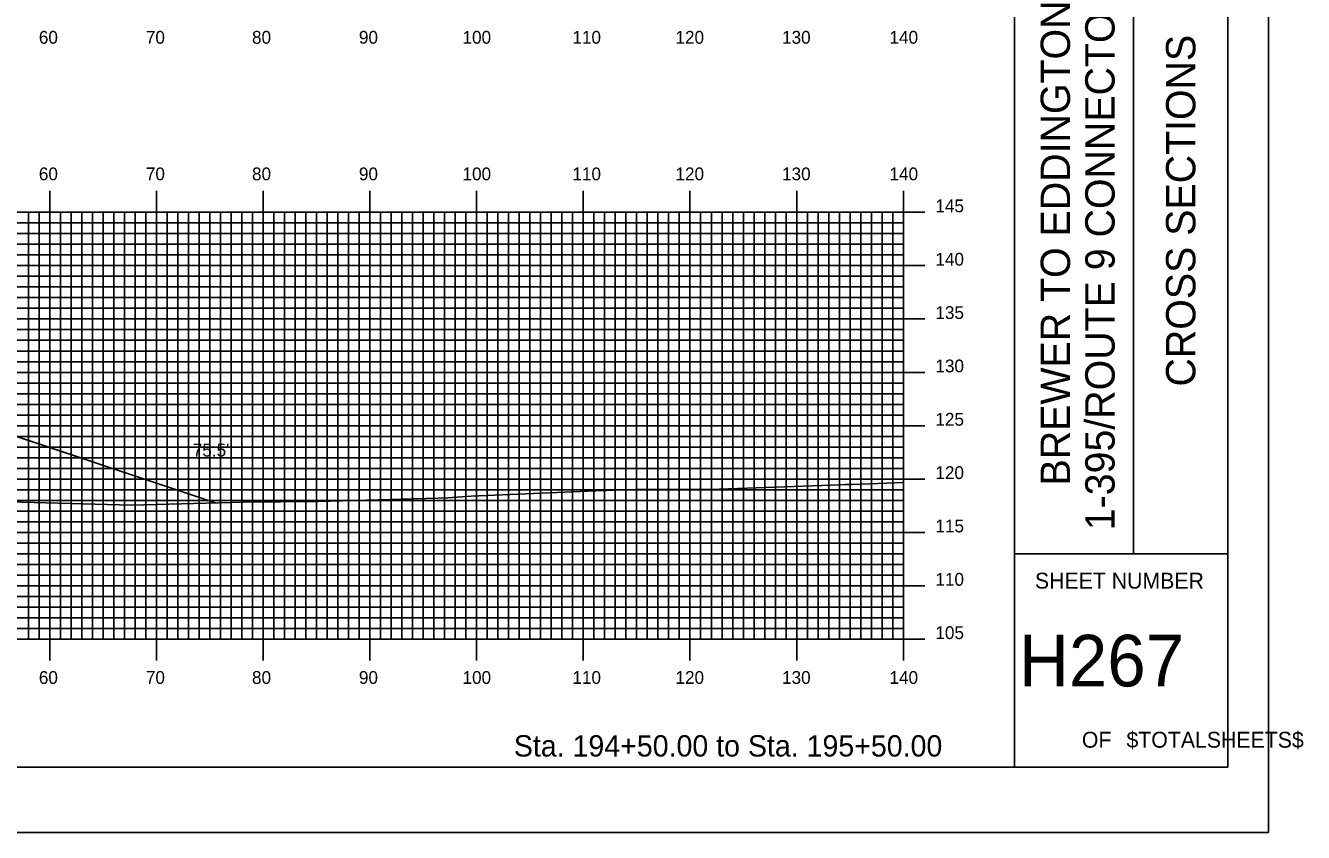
# Model space of a CAD drawing. Extents: x 1789337 to 1789680, y 442591 to 442811.
# Drawn here: x 1789560.4 to 1789680.2, y 442590.5 to 442666.2 of the extents above; entities that cross this region are included whole.
import ezdxf

# ---------------------------------------------------------------- set-up
doc = ezdxf.new("R2010")
doc.units = 0
for name, color, linetype in [('BORDER', 7, 'Continuous'), ('D_Roadway_Centerline', 7, 'Continuous'), ('D_Roadway_SlopeLines', 7, 'Continuous'), ('D_Text_Standard', 7, 'Continuous'), ('H_V ANNOTATION', 7, 'Continuous'), ('MAJOR', 7, 'Continuous'), ('MINOR', 7, 'Continuous'), ('PLOT BOUNDARY', 7, 'Continuous'), ('S_Roadway_Centerline', 7, 'Continuous')]:
    doc.layers.add(name, color=color, linetype=linetype)

msp = doc.modelspace()

# ---------------------------------------------------------------- linework, layer by layer
at = {"layer": 'BORDER'}
for p, q in [((1789653.07, 442596.67), (1789653.07, 442806.67)), ((1789664.25, 442616.67), (1789664.25, 442686.67)), ((1789653.07, 442616.67), (1789673.07, 442616.67))]:
    msp.add_line(p, q, dxfattribs=at)
msp.add_lwpolyline([(1789353.07, 442596.67), (1789673.07, 442596.67), (1789673.07, 442806.67), (1789353.07, 442806.67)], close=True, dxfattribs=at)
at = {"layer": 'D_Roadway_Centerline'}
msp.add_lwpolyline([(1789424.26, 442619.51), (1789472.46, 442635.96), (1789479.67, 442638.42), (1789482.67, 442638.54), (1789490.67, 442638.86), (1789502.67, 442639.12), (1789514.67, 442639.39), (1789522.67, 442639.07), (1789525.67, 442638.95), (1789532.95, 442636.52), (1789578.2, 442621.44)], dxfattribs=at)
at = {"layer": 'D_Roadway_SlopeLines'}
msp.add_lwpolyline([(1789525.67, 442638.95), (1789578.2, 442621.44)], dxfattribs=at)
at = {"layer": 'MAJOR'}
for p, q in [((1789562.67, 442650.67), (1789562.67, 442648.67)), ((1789572.67, 442650.67), (1789572.67, 442648.67)), ((1789582.67, 442650.67), (1789582.67, 442648.67)), ((1789592.67, 442650.67), (1789592.67, 442648.67)), ((1789602.67, 442650.67), (1789602.67, 442648.67)), ((1789612.67, 442650.67), (1789612.67, 442648.67)), ((1789622.67, 442650.67), (1789622.67, 442648.67)), ((1789632.67, 442650.67), (1789632.67, 442648.67)), ((1789642.67, 442650.67), (1789642.67, 442648.67)), ((1789362.67, 442648.67), (1789642.67, 442648.67)), ((1789362.67, 442648.67), (1789642.67, 442648.67)), ((1789562.67, 442608.67), (1789562.67, 442648.67)), ((1789572.67, 442608.67), (1789572.67, 442648.67)), ((1789582.67, 442608.67), (1789582.67, 442648.67)), ((1789592.67, 442608.67), (1789592.67, 442648.67)), ((1789602.67, 442608.67), (1789602.67, 442648.67)), ((1789612.67, 442608.67), (1789612.67, 442648.67)), ((1789622.67, 442608.67), (1789622.67, 442648.67)), ((1789632.67, 442608.67), (1789632.67, 442648.67)), ((1789644.67, 442648.67), (1789640.67, 442648.67)), ((1789642.67, 442608.67), (1789642.67, 442648.67)), ((1789642.67, 442608.67), (1789642.67, 442648.67)), ((1789362.67, 442643.67), (1789642.67, 442643.67)), ((1789644.67, 442643.67), (1789640.67, 442643.67)), ((1789362.67, 442638.67), (1789642.67, 442638.67)), ((1789644.67, 442638.67), (1789640.67, 442638.67)), ((1789362.67, 442633.67), (1789642.67, 442633.67)), ((1789644.67, 442633.67), (1789640.67, 442633.67)), ((1789362.67, 442628.67), (1789642.67, 442628.67)), ((1789644.67, 442628.67), (1789640.67, 442628.67)), ((1789362.67, 442623.67), (1789642.67, 442623.67)), ((1789644.67, 442623.67), (1789640.67, 442623.67)), ((1789362.67, 442618.67), (1789642.67, 442618.67)), ((1789644.67, 442618.67), (1789640.67, 442618.67)), ((1789362.67, 442613.67), (1789642.67, 442613.67)), ((1789644.67, 442613.67), (1789640.67, 442613.67)), ((1789362.67, 442608.67), (1789642.67, 442608.67)), ((1789362.67, 442608.67), (1789642.67, 442608.67)), ((1789562.67, 442606.66), (1789562.67, 442608.67)), ((1789572.67, 442606.66), (1789572.67, 442608.67)), ((1789582.67, 442606.66), (1789582.67, 442608.67)), ((1789592.67, 442606.66), (1789592.67, 442608.67)), ((1789602.67, 442606.66), (1789602.67, 442608.67)), ((1789612.67, 442606.66), (1789612.67, 442608.67)), ((1789622.67, 442606.66), (1789622.67, 442608.67)), ((1789632.67, 442606.66), (1789632.67, 442608.67)), ((1789644.67, 442608.67), (1789640.67, 442608.67)), ((1789642.67, 442606.66), (1789642.67, 442608.67))]:
    msp.add_line(p, q, dxfattribs=at)
at = {"layer": 'MINOR'}
for p, q in [((1789362.67, 442647.67), (1789642.67, 442647.67)), ((1789560.67, 442608.67), (1789560.67, 442648.67)), ((1789561.67, 442608.67), (1789561.67, 442648.67)), ((1789563.67, 442608.67), (1789563.67, 442648.67)), ((1789564.67, 442608.67), (1789564.67, 442648.67)), ((1789565.67, 442608.67), (1789565.67, 442648.67)), ((1789566.67, 442608.67), (1789566.67, 442648.67)), ((1789567.67, 442608.67), (1789567.67, 442648.67)), ((1789568.67, 442608.67), (1789568.67, 442648.67)), ((1789569.67, 442608.67), (1789569.67, 442648.67)), ((1789570.67, 442608.67), (1789570.67, 442648.67)), ((1789571.67, 442608.67), (1789571.67, 442648.67)), ((1789573.67, 442608.67), (1789573.67, 442648.67)), ((1789574.67, 442608.67), (1789574.67, 442648.67)), ((1789575.67, 442608.67), (1789575.67, 442648.67)), ((1789576.67, 442608.67), (1789576.67, 442648.67)), ((1789577.67, 442608.67), (1789577.67, 442648.67)), ((1789578.67, 442608.67), (1789578.67, 442648.67)), ((1789579.67, 442608.67), (1789579.67, 442648.67)), ((1789580.67, 442608.67), (1789580.67, 442648.67)), ((1789581.67, 442608.67), (1789581.67, 442648.67)), ((1789583.67, 442608.67), (1789583.67, 442648.67)), ((1789584.67, 442608.67), (1789584.67, 442648.67)), ((1789585.67, 442608.67), (1789585.67, 442648.67)), ((1789586.67, 442608.67), (1789586.67, 442648.67)), ((1789587.67, 442608.67), (1789587.67, 442648.67)), ((1789588.67, 442608.67), (1789588.67, 442648.67)), ((1789589.67, 442608.67), (1789589.67, 442648.67)), ((1789590.67, 442608.67), (1789590.67, 442648.67)), ((1789591.67, 442608.67), (1789591.67, 442648.67)), ((1789593.67, 442608.67), (1789593.67, 442648.67)), ((1789594.67, 442608.67), (1789594.67, 442648.67)), ((1789595.67, 442608.67), (1789595.67, 442648.67)), ((1789596.67, 442608.67), (1789596.67, 442648.67)), ((1789597.67, 442608.67), (1789597.67, 442648.67)), ((1789598.67, 442608.67), (1789598.67, 442648.67)), ((1789599.67, 442608.67), (1789599.67, 442648.67)), ((1789600.67, 442608.67), (1789600.67, 442648.67)), ((1789601.67, 442608.67), (1789601.67, 442648.67)), ((1789603.67, 442608.67), (1789603.67, 442648.67)), ((1789604.67, 442608.67), (1789604.67, 442648.67)), ((1789605.67, 442608.67), (1789605.67, 442648.67)), ((1789606.67, 442608.67), (1789606.67, 442648.67)), ((1789607.67, 442608.67), (1789607.67, 442648.67)), ((1789608.67, 442608.67), (1789608.67, 442648.67)), ((1789609.67, 442608.67), (1789609.67, 442648.67)), ((1789610.67, 442608.67), (1789610.67, 442648.67)), ((1789611.67, 442608.67), (1789611.67, 442648.67)), ((1789613.67, 442608.67), (1789613.67, 442648.67)), ((1789614.67, 442608.67), (1789614.67, 442648.67)), ((1789615.67, 442608.67), (1789615.67, 442648.67)), ((1789616.67, 442608.67), (1789616.67, 442648.67)), ((1789617.67, 442608.67), (1789617.67, 442648.67)), ((1789618.67, 442608.67), (1789618.67, 442648.67)), ((1789619.67, 442608.67), (1789619.67, 442648.67)), ((1789620.67, 442608.67), (1789620.67, 442648.67)), ((1789621.67, 442608.67), (1789621.67, 442648.67)), ((1789623.67, 442608.67), (1789623.67, 442648.67)), ((1789624.67, 442608.67), (1789624.67, 442648.67)), ((1789625.67, 442608.67), (1789625.67, 442648.67)), ((1789626.67, 442608.67), (1789626.67, 442648.67)), ((1789627.67, 442608.67), (1789627.67, 442648.67)), ((1789628.67, 442608.67), (1789628.67, 442648.67)), ((1789629.67, 442608.67), (1789629.67, 442648.67)), ((1789630.67, 442608.67), (1789630.67, 442648.67)), ((1789631.67, 442608.67), (1789631.67, 442648.67)), ((1789633.67, 442608.67), (1789633.67, 442648.67)), ((1789634.67, 442608.67), (1789634.67, 442648.67)), ((1789635.67, 442608.67), (1789635.67, 442648.67)), ((1789636.67, 442608.67), (1789636.67, 442648.67)), ((1789637.67, 442608.67), (1789637.67, 442648.67)), ((1789638.67, 442608.67), (1789638.67, 442648.67)), ((1789639.67, 442608.67), (1789639.67, 442648.67)), ((1789640.67, 442608.67), (1789640.67, 442648.67)), ((1789642.67, 442647.67), (1789640.67, 442647.67)), ((1789641.67, 442608.67), (1789641.67, 442648.67)), ((1789362.67, 442646.67), (1789642.67, 442646.67)), ((1789642.67, 442646.67), (1789640.67, 442646.67)), ((1789362.67, 442645.67), (1789642.67, 442645.67)), ((1789642.67, 442645.67), (1789640.67, 442645.67)), ((1789362.67, 442644.67), (1789642.67, 442644.67)), ((1789642.67, 442644.67), (1789640.67, 442644.67)), ((1789362.67, 442642.67), (1789642.67, 442642.67)), ((1789362.67, 442641.67), (1789642.67, 442641.67)), ((1789642.67, 442642.67), (1789640.67, 442642.67)), ((1789642.67, 442641.67), (1789640.67, 442641.67)), ((1789362.67, 442640.67), (1789642.67, 442640.67)), ((1789642.67, 442640.67), (1789640.67, 442640.67)), ((1789362.67, 442639.67), (1789642.67, 442639.67)), ((1789642.67, 442639.67), (1789640.67, 442639.67)), ((1789362.67, 442637.67), (1789642.67, 442637.67)), ((1789642.67, 442637.67), (1789640.67, 442637.67)), ((1789362.67, 442636.67), (1789642.67, 442636.67)), ((1789362.67, 442635.67), (1789642.67, 442635.67)), ((1789642.67, 442636.67), (1789640.67, 442636.67)), ((1789642.67, 442635.67), (1789640.67, 442635.67)), ((1789362.67, 442634.67), (1789642.67, 442634.67)), ((1789642.67, 442634.67), (1789640.67, 442634.67)), ((1789362.67, 442632.67), (1789642.67, 442632.67)), ((1789642.67, 442632.67), (1789640.67, 442632.67)), ((1789362.67, 442631.67), (1789642.67, 442631.67)), ((1789642.67, 442631.67), (1789640.67, 442631.67)), ((1789362.67, 442630.67), (1789642.67, 442630.67)), ((1789362.67, 442629.67), (1789642.67, 442629.67)), ((1789642.67, 442630.67), (1789640.67, 442630.67)), ((1789642.67, 442629.67), (1789640.67, 442629.67)), ((1789362.67, 442627.67), (1789642.67, 442627.67)), ((1789642.67, 442627.67), (1789640.67, 442627.67)), ((1789362.67, 442626.67), (1789642.67, 442626.67)), ((1789642.67, 442626.67), (1789640.67, 442626.67)), ((1789362.67, 442625.67), (1789642.67, 442625.67)), ((1789642.67, 442625.67), (1789640.67, 442625.67)), ((1789362.67, 442624.67), (1789642.67, 442624.67)), ((1789642.67, 442624.67), (1789640.67, 442624.67)), ((1789362.67, 442622.67), (1789642.67, 442622.67)), ((1789642.67, 442622.67), (1789640.67, 442622.67)), ((1789362.67, 442621.67), (1789642.67, 442621.67)), ((1789642.67, 442621.67), (1789640.67, 442621.67)), ((1789362.67, 442620.67), (1789642.67, 442620.67)), ((1789642.67, 442620.67), (1789640.67, 442620.67)), ((1789362.67, 442619.67), (1789642.67, 442619.67)), ((1789642.67, 442619.67), (1789640.67, 442619.67)), ((1789362.67, 442617.67), (1789642.67, 442617.67)), ((1789642.67, 442617.67), (1789640.67, 442617.67)), ((1789362.67, 442616.67), (1789642.67, 442616.67)), ((1789642.67, 442616.67), (1789640.67, 442616.67)), ((1789362.67, 442615.67), (1789642.67, 442615.67)), ((1789642.67, 442615.67), (1789640.67, 442615.67)), ((1789362.67, 442614.67), (1789642.67, 442614.67)), ((1789642.67, 442614.67), (1789640.67, 442614.67)), ((1789362.67, 442612.67), (1789642.67, 442612.67)), ((1789362.67, 442611.67), (1789642.67, 442611.67)), ((1789642.67, 442612.67), (1789640.67, 442612.67)), ((1789642.67, 442611.67), (1789640.67, 442611.67)), ((1789362.67, 442610.67), (1789642.67, 442610.67)), ((1789642.67, 442610.67), (1789640.67, 442610.67)), ((1789362.67, 442609.67), (1789642.67, 442609.67)), ((1789642.67, 442609.67), (1789640.67, 442609.67))]:
    msp.add_line(p, q, dxfattribs=at)
at = {"layer": 'PLOT BOUNDARY'}
msp.add_lwpolyline([(1789336.88, 442590.55), (1789676.88, 442590.55), (1789676.88, 442810.55), (1789336.88, 442810.55)], close=True, dxfattribs=at)
at = {"layer": 'S_Roadway_Centerline'}
msp.add_lwpolyline([(1789554.37, 442621.66), (1789570.33, 442621.21), (1789580.79, 442621.51), (1789587.82, 442621.58), (1789599.04, 442621.89), (1789599.96, 442621.92), (1789602.16, 442622.05), (1789613.83, 442622.55), (1789618.62, 442622.73), (1789624.52, 442622.69), (1789636.79, 442623.14), (1789637.19, 442623.17), (1789637.91, 442623.17), (1789642.67, 442623.34)], dxfattribs=at)

# ---------------------------------------------------------------- texts
at = {"layer": 'BORDER'}
for s, p in [('1-395/ROUTE 9 CONNECTOR', (1789662.47, 442618.87)), ('BREWER TO EDDINGTON', (1789658.29, 442623.07)), ('CROSS SECTIONS', (1789670.04, 442632.34))]:
    msp.add_text(s, height=2.7557, rotation=90, dxfattribs=at).set_placement(p)
for s, height, p in [('SHEET NUMBER', 1.4905, (1789655, 442613.4)), ('H267', 4.839, (1789653.51, 442604.23)), ('OF', 1.491, (1789659.4, 442598.49)), ('$TOTALSHEETS$', 1.4905, (1789663.58, 442598.49))]:
    msp.add_text(s, height=height, dxfattribs=at).set_placement(p)
at = {"layer": 'D_Text_Standard'}
msp.add_text("75.5'", height=1.2, dxfattribs=at).set_placement((1789576.07, 442625.78))
at = {"layer": 'H_V ANNOTATION'}
for s, height, p in [('60', 1.2, (1789561.64, 442664.47)), ('70', 1.2, (1789571.67, 442664.47)), ('80', 1.2, (1789581.62, 442664.47)), ('90', 1.2, (1789591.64, 442664.47)), ('100', 1.2, (1789601.35, 442664.47)), ('110', 1.2, (1789611.65, 442664.47)), ('120', 1.2, (1789621.31, 442664.47)), ('130', 1.2, (1789631.3, 442664.47)), ('140', 1.2, (1789641.37, 442664.47)), ('60', 1.2, (1789561.64, 442651.67)), ('70', 1.2, (1789571.67, 442651.67)), ('80', 1.2, (1789581.62, 442651.67)), ('90', 1.2, (1789591.64, 442651.67)), ('100', 1.2, (1789601.35, 442651.67)), ('110', 1.2, (1789611.65, 442651.67)), ('120', 1.2, (1789621.31, 442651.67)), ('130', 1.2, (1789631.3, 442651.67)), ('140', 1.2, (1789641.37, 442651.67)), ('145', 1.2, (1789645.67, 442648.67)), ('140', 1.2, (1789645.67, 442643.67)), ('135', 1.2, (1789645.67, 442638.67)), ('130', 1.2, (1789645.67, 442633.67)), ('125', 1.2, (1789645.67, 442628.67)), ('120', 1.2, (1789645.67, 442623.67)), ('115', 1.2, (1789645.67, 442618.67)), ('110', 1.2, (1789645.67, 442613.67)), ('105', 1.2, (1789645.67, 442608.67)), ('60', 1.2, (1789561.64, 442604.47)), ('70', 1.2, (1789571.67, 442604.47)), ('80', 1.2, (1789581.62, 442604.47)), ('90', 1.2, (1789591.64, 442604.47)), ('100', 1.2, (1789601.35, 442604.47)), ('110', 1.2, (1789611.65, 442604.47)), ('120', 1.2, (1789621.31, 442604.47)), ('130', 1.2, (1789631.3, 442604.47)), ('140', 1.2, (1789641.37, 442604.47)), ('Sta. 194+50.00 to Sta. 195+50.00', 2.0004, (1789606.16, 442597.66))]:
    msp.add_text(s, height=height, dxfattribs=at).set_placement(p)

doc.saveas('drawing.dxf')
